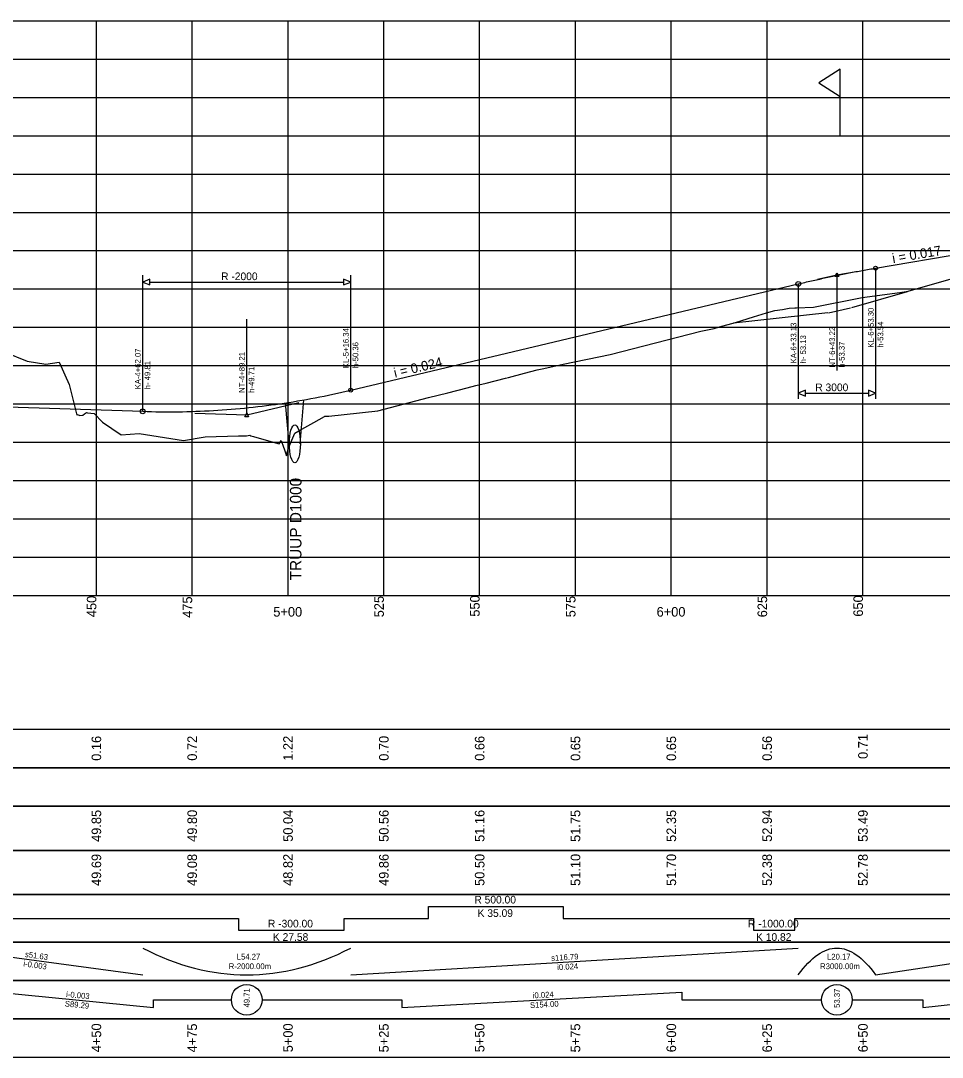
# Model space of a CAD drawing. Extents: x 655100 to 703495, y 6445581 to 6476602.
# Drawn here: x 669739.6 to 669980, y 6465749.1 to 6466019.6 of the extents above; entities that cross this region are included whole.
import ezdxf

# ---------------------------------------------------------------- set-up
doc = ezdxf.new("R2010")
doc.units = 0
for name, color, linetype in [('1_truup proj', 7, 'Continuous'), ('54', 7, 'Continuous'), ('Level 25', 7, 'Continuous'), ('Level 6', 7, 'Continuous'), ('MAAMUDEL', 7, 'Continuous'), ('Profile', 7, 'Continuous'), ('Profile Annotation', 7, 'Continuous'), ('Prop Vertical Alignment', 7, 'Continuous'), ('Prop_Benching', 7, 'Continuous'), ('TRUUP', 7, 'Continuous')]:
    doc.layers.add(name, color=color, linetype=linetype)

msp = doc.modelspace()

# ---------------------------------------------------------------- linework, layer by layer
at = {"layer": '1_truup proj'}
msp.add_line((669950.32, 6465943.38), (669956.02, 6465944.62), dxfattribs=at)
at = {"layer": '54'}
for points in [[(669299.3, 6465824.57), (670219.3, 6465824.57), (670219.3, 6465834.57), (669299.3, 6465834.57)], [(669299.3, 6465814.57), (670219.3, 6465814.57), (670219.3, 6465824.57), (669299.3, 6465824.57)], [(669299.3, 6465803.07), (670219.3, 6465803.07), (670219.3, 6465814.57), (669299.3, 6465814.57)], [(669299.3, 6465791.57), (670219.3, 6465791.57), (670219.3, 6465803.07), (669299.3, 6465803.07)], [(669299.3, 6465779.07), (670219.3, 6465779.07), (670219.3, 6465791.57), (669299.3, 6465791.57)], [(669299.3, 6465769.07), (670219.3, 6465769.07), (670219.3, 6465779.07), (669299.3, 6465779.07)], [(669299.3, 6465759.07), (670219.3, 6465759.07), (670219.3, 6465769.07), (669299.3, 6465769.07)], [(669299.3, 6465749.07), (670219.3, 6465749.07), (670219.3, 6465759.07), (669299.3, 6465759.07)]]:
    msp.add_lwpolyline(points, close=True, dxfattribs=at)
for points in [[(669759.3, 6465834.57), (669759.3, 6465834.57)], [(669784.3, 6465834.57), (669784.3, 6465834.57)], [(669809.3, 6465834.57), (669809.3, 6465834.57)], [(669834.3, 6465834.57), (669834.3, 6465834.57)], [(669859.3, 6465834.57), (669859.3, 6465834.57)], [(669884.3, 6465834.57), (669884.3, 6465834.57)], [(669909.3, 6465834.57), (669909.3, 6465834.57)], [(669934.3, 6465834.57), (669934.3, 6465834.57)], [(669959.3, 6465834.57), (669959.3, 6465834.57)], [(669759.3, 6465824.57), (669759.3, 6465824.57)], [(669784.3, 6465824.57), (669784.3, 6465824.57)], [(669809.3, 6465824.57), (669809.3, 6465824.57)], [(669834.3, 6465824.57), (669834.3, 6465824.57)], [(669859.3, 6465824.57), (669859.3, 6465824.57)], [(669884.3, 6465824.57), (669884.3, 6465824.57)], [(669909.3, 6465824.57), (669909.3, 6465824.57)], [(669934.3, 6465824.57), (669934.3, 6465824.57)], [(669959.3, 6465824.57), (669959.3, 6465824.57)], [(669759.3, 6465814.57), (669759.3, 6465814.57)], [(669784.3, 6465814.57), (669784.3, 6465814.57)], [(669809.3, 6465814.57), (669809.3, 6465814.57)], [(669834.3, 6465814.57), (669834.3, 6465814.57)], [(669859.3, 6465814.57), (669859.3, 6465814.57)], [(669884.3, 6465814.57), (669884.3, 6465814.57)], [(669909.3, 6465814.57), (669909.3, 6465814.57)], [(669934.3, 6465814.57), (669934.3, 6465814.57)], [(669959.3, 6465814.57), (669959.3, 6465814.57)], [(669759.3, 6465803.07), (669759.3, 6465803.07)], [(669784.3, 6465803.07), (669784.3, 6465803.07)], [(669809.3, 6465803.07), (669809.3, 6465803.07)], [(669834.3, 6465803.07), (669834.3, 6465803.07)], [(669859.3, 6465803.07), (669859.3, 6465803.07)], [(669884.3, 6465803.07), (669884.3, 6465803.07)], [(669909.3, 6465803.07), (669909.3, 6465803.07)], [(669934.3, 6465803.07), (669934.3, 6465803.07)], [(669959.3, 6465803.07), (669959.3, 6465803.07)], [(669796.34, 6465791.57), (669796.34, 6465791.57)], [(669823.91, 6465791.57), (669823.91, 6465791.57)], [(669845.97, 6465791.57), (669845.97, 6465791.57)], [(669881.07, 6465791.57), (669881.07, 6465791.57)], [(669930.74, 6465791.57), (669930.74, 6465791.57)], [(669941.56, 6465791.57), (669941.56, 6465791.57)], [(669771.38, 6465779.07), (669771.38, 6465779.07)], [(669825.65, 6465779.07), (669825.65, 6465779.07)], [(669942.44, 6465779.07), (669942.44, 6465779.07)], [(669962.61, 6465779.07), (669962.61, 6465779.07)], [(669771.38, 6465769.07), (669771.38, 6465769.07)], [(669825.65, 6465769.07), (669825.65, 6465769.07)], [(669942.44, 6465769.07), (669942.44, 6465769.07)], [(669962.61, 6465769.07), (669962.61, 6465769.07)], [(669759.3, 6465759.07), (669759.3, 6465759.07)], [(669784.3, 6465759.07), (669784.3, 6465759.07)], [(669809.3, 6465759.07), (669809.3, 6465759.07)], [(669834.3, 6465759.07), (669834.3, 6465759.07)], [(669859.3, 6465759.07), (669859.3, 6465759.07)], [(669884.3, 6465759.07), (669884.3, 6465759.07)], [(669909.3, 6465759.07), (669909.3, 6465759.07)], [(669934.3, 6465759.07), (669934.3, 6465759.07)], [(669959.3, 6465759.07), (669959.3, 6465759.07)]]:
    msp.add_lwpolyline(points, dxfattribs=at)
at = {"layer": 'Level 25'}
msp.add_lwpolyline([(669953.33, 6465989.57), (669953.33, 6466006.92), (669947.83, 6466003.39), (669953.34, 6465999.84)], dxfattribs=at)
at = {"layer": 'Level 6'}
msp.add_lwpolyline([(669735.24, 6465933.15), (669741.27, 6465930.69), (669746.12, 6465929.95), (669749.62, 6465930.47), (669752.22, 6465924.63), (669754.24, 6465916.66), (669754.4, 6465916.8), (669755, 6465916.57), (669755.77, 6465916.61), (669756.2, 6465916.99), (669756.75, 6465917.32), (669757.02, 6465917.23), (669758.72, 6465917.05), (669758.73, 6465917.05), (669760.91, 6465914.85), (669765.78, 6465911.54), (669770.47, 6465911.88), (669782.03, 6465910.02), (669787.71, 6465911.02), (669796.34, 6465911.22), (669798.46, 6465911.27), (669799.36, 6465911.39), (669799.58, 6465911.25), (669800.28, 6465911.06), (669804.22, 6465909.94), (669807, 6465909.15), (669807.54, 6465910.01), (669808.16, 6465908.29), (669808.33, 6465907.82), (669808.89, 6465906.03), (669809.35, 6465907.88), (669811.08, 6465911.93), (669812.1, 6465912.51), (669816.04, 6465914.74), (669818.84, 6465916.32), (669818.89, 6465916.35), (669819.01, 6465916.36), (669819.76, 6465916.4), (669819.98, 6465916.42), (669823.91, 6465916.83), (669832.71, 6465917.76), (669845.97, 6465921.21), (669850.99, 6465922.51), (669856, 6465923.78), (669858.33, 6465924.36), (669861.01, 6465925.03), (669866.03, 6465926.27), (669866.79, 6465926.45), (669871.04, 6465927.59), (669874.3, 6465928.44), (669876.05, 6465928.83), (669881.07, 6465929.91), (669893.38, 6465932.51), (669917.04, 6465938.55), (669920.51, 6465939.29), (669921.87, 6465939.71), (669926.03, 6465940.85), (669930.74, 6465942.31), (669934.14, 6465943.37), (669936.27, 6465943.94), (669938.33, 6465944.25), (669940.04, 6465944.58), (669941.56, 6465944.63), (669941.96, 6465944.64), (669946.4, 6465944.84), (669959.13, 6465947.34), (669968.96, 6465948.68), (669971.13, 6465949.01), (669979.86, 6465951.5), (669993.44, 6465955.39)], dxfattribs=at)
at = {"layer": 'MAAMUDEL'}
for p, q in [((669956.43, 6465944.71), (669970.96, 6465948.95)), ((669950.16, 6465943.31), (669925.49, 6465940.63))]:
    msp.add_line(p, q, dxfattribs=at)
at = {"layer": 'Profile'}
for p, q in [((669309.3, 6466019.57), (670209.3, 6466019.57)), ((669309.3, 6466019.57), (670209.3, 6466019.57)), ((669759.3, 6465869.57), (669759.3, 6466019.57)), ((669784.3, 6465869.57), (669784.3, 6466019.57)), ((669809.3, 6465869.57), (669809.3, 6466019.57)), ((669834.3, 6465869.57), (669834.3, 6466019.57)), ((669859.3, 6465869.57), (669859.3, 6466019.57)), ((669884.3, 6465869.57), (669884.3, 6466019.57)), ((669909.3, 6465869.57), (669909.3, 6466019.57)), ((669934.3, 6465869.57), (669934.3, 6466019.57)), ((669959.3, 6465869.57), (669959.3, 6466019.57)), ((669309.3, 6466009.57), (670209.3, 6466009.57)), ((669309.3, 6465999.57), (670209.3, 6465999.57)), ((669309.3, 6465989.57), (670209.3, 6465989.57)), ((669309.3, 6465979.57), (670209.3, 6465979.57)), ((669309.3, 6465969.57), (670209.3, 6465969.57)), ((669309.3, 6465959.57), (670209.3, 6465959.57)), ((669309.3, 6465949.57), (670209.3, 6465949.57)), ((669309.3, 6465939.57), (670209.3, 6465939.57)), ((669309.3, 6465929.57), (670209.3, 6465929.57)), ((669309.3, 6465919.57), (670209.3, 6465919.57)), ((669309.3, 6465909.57), (670209.3, 6465909.57)), ((669309.3, 6465899.57), (670209.3, 6465899.57)), ((669309.3, 6465889.57), (670209.3, 6465889.57)), ((669309.3, 6465879.57), (670209.3, 6465879.57)), ((669309.3, 6465869.57), (670209.3, 6465869.57))]:
    msp.add_line(p, q, dxfattribs=at)
at = {"layer": 'Profile Annotation'}
for points in [[(669648.62, 6465785.32), (669796.34, 6465785.32), (669796.34, 6465782.2), (669823.91, 6465782.2), (669823.91, 6465785.32), (669845.97, 6465785.32), (669845.97, 6465788.45), (669881.07, 6465788.45), (669881.07, 6465785.32), (669930.74, 6465785.32), (669930.74, 6465782.2), (669941.56, 6465782.2), (669941.56, 6465785.32), (669993.44, 6465785.32), (669993.44, 6465782.2), (670015.52, 6465782.2), (670015.52, 6465785.32), (670050.86, 6465785.32), (670050.86, 6465782.2), (670195.72, 6465782.2), (670195.72, 6465785.32), (670204.27, 6465785.32)], [(669719.74, 6465777.57), (669771.38, 6465770.57)], [(669771.38, 6465777.57), (669773.07, 6465776.73), (669774.77, 6465775.93), (669776.46, 6465775.19), (669778.16, 6465774.51), (669779.86, 6465773.88), (669781.55, 6465773.31), (669783.25, 6465772.79), (669784.94, 6465772.32), (669786.64, 6465771.91), (669788.34, 6465771.56), (669790.03, 6465771.26), (669791.73, 6465771.01), (669793.42, 6465770.82), (669795.12, 6465770.68), (669796.82, 6465770.6), (669800.21, 6465770.6), (669801.9, 6465770.68), (669803.6, 6465770.82), (669805.3, 6465771.01), (669806.99, 6465771.26), (669808.69, 6465771.56), (669810.39, 6465771.91), (669812.08, 6465772.32), (669813.78, 6465772.79), (669815.47, 6465773.31), (669817.17, 6465773.88), (669818.87, 6465774.51), (669820.56, 6465775.19), (669822.26, 6465775.93), (669823.95, 6465776.73), (669825.65, 6465777.57)], [(669825.65, 6465770.57), (669942.44, 6465777.57)], [(669942.44, 6465770.57), (669943.07, 6465771.42), (669943.7, 6465772.21), (669944.33, 6465772.95), (669944.96, 6465773.64), (669945.59, 6465774.26), (669946.22, 6465774.84), (669946.85, 6465775.36), (669947.48, 6465775.82), (669948.11, 6465776.23), (669948.74, 6465776.59), (669949.37, 6465776.89), (669950, 6465777.14), (669950.63, 6465777.33), (669951.26, 6465777.46), (669951.89, 6465777.55), (669953.15, 6465777.55), (669953.78, 6465777.46), (669954.41, 6465777.33), (669955.04, 6465777.14), (669955.67, 6465776.89), (669956.3, 6465776.59), (669956.93, 6465776.23), (669957.57, 6465775.82), (669958.2, 6465775.36), (669958.83, 6465774.84), (669959.46, 6465774.26), (669960.09, 6465773.64), (669960.72, 6465772.95), (669961.35, 6465772.21), (669961.98, 6465771.42), (669962.61, 6465770.57)], [(669962.61, 6465770.57), (670008.95, 6465777.57)], [(669713.23, 6465764.07), (669733.55, 6465764.07), (669733.55, 6465766.07), (669774.19, 6465762.07), (669774.19, 6465764.07), (669794.52, 6465764.07)], [(669802.52, 6465764.07), (669839.02, 6465764.07), (669839.02, 6465762.07), (669912.02, 6465766.07), (669912.02, 6465764.07), (669948.52, 6465764.07)], [(669956.52, 6465764.07), (669974.9, 6465764.07), (669974.9, 6465762.07), (670011.65, 6465766.07), (670011.65, 6465764.07), (670030.02, 6465764.07)]]:
    msp.add_lwpolyline(points, dxfattribs=at)
for centre in [(669798.52, 6465764.07), (669952.52, 6465764.07)]:
    msp.add_circle(centre, 4, dxfattribs=at)
at = {"layer": 'Prop Vertical Alignment'}
for p, q in [((669962.61, 6465955.01), (670008.95, 6465962.9)), ((669952.52, 6465953.29), (669957.56, 6465954.15)), ((669962.61, 6465955.01), (669962.61, 6465950.01)), ((669962.61, 6465955.01), (669962.61, 6465920.9)), ((669771.38, 6465917.64), (669771.38, 6465953.16)), ((669825.65, 6465923.16), (669825.65, 6465953.16)), ((669825.65, 6465923.16), (669942.44, 6465950.9)), ((669942.44, 6465950.9), (669942.44, 6465945.9)), ((669942.44, 6465950.9), (669942.44, 6465920.9)), ((669947.48, 6465952.1), (669952.52, 6465953.29)), ((669952.52, 6465952.61), (669952.52, 6465928.29)), ((669962.61, 6465950.01), (669962.61, 6465933.51)), ((669942.44, 6465945.9), (669942.44, 6465929.4)), ((669825.65, 6465928.16), (669825.65, 6465944.66)), ((669798.52, 6465921.72), (669798.52, 6465941.72)), ((669771.38, 6465922.64), (669771.38, 6465939.14)), ((669825.65, 6465923.16), (669825.65, 6465928.16)), ((669771.38, 6465917.64), (669771.38, 6465922.64)), ((669798.52, 6465916.72), (669798.52, 6465921.72)), ((669719.74, 6465919.39), (669771.38, 6465917.64)), ((669798.52, 6465916.72), (669812.08, 6465919.94)), ((669784.95, 6465917.18), (669798.52, 6465916.72))]:
    msp.add_line(p, q, dxfattribs=at)
for points in [[(669942.44, 6465950.9), (669942.86, 6465951), (669943.29, 6465951.1), (669943.72, 6465951.2), (669944.15, 6465951.3), (669944.58, 6465951.4), (669945.01, 6465951.5), (669945.44, 6465951.6), (669945.87, 6465951.69), (669946.3, 6465951.79), (669946.73, 6465951.89), (669947.16, 6465951.98), (669947.59, 6465952.08), (669948.01, 6465952.17), (669948.44, 6465952.26), (669948.87, 6465952.36), (669949.3, 6465952.45), (669949.73, 6465952.54), (669950.16, 6465952.63), (669950.59, 6465952.72), (669951.02, 6465952.81), (669951.45, 6465952.9), (669951.88, 6465952.99), (669952.31, 6465953.08), (669952.74, 6465953.17), (669953.17, 6465953.25), (669953.59, 6465953.34), (669954.02, 6465953.43), (669954.45, 6465953.51), (669954.88, 6465953.6), (669955.31, 6465953.68), (669955.74, 6465953.76), (669956.17, 6465953.85), (669956.6, 6465953.93), (669957.03, 6465954.01), (669957.46, 6465954.09), (669957.89, 6465954.17), (669958.32, 6465954.25), (669958.75, 6465954.33), (669959.17, 6465954.41), (669959.6, 6465954.48), (669960.03, 6465954.56), (669960.46, 6465954.64), (669960.89, 6465954.71), (669961.32, 6465954.79), (669961.75, 6465954.86), (669962.18, 6465954.94), (669962.61, 6465955.01)], [(669773.22, 6465951.38), (669823.8, 6465951.38)], [(669771.38, 6465917.64), (669772.53, 6465917.6), (669773.69, 6465917.57), (669774.84, 6465917.55), (669776, 6465917.53), (669777.15, 6465917.52), (669778.3, 6465917.52), (669779.46, 6465917.53), (669780.61, 6465917.54), (669781.77, 6465917.55), (669782.92, 6465917.58), (669784.08, 6465917.61), (669785.23, 6465917.65), (669786.39, 6465917.69), (669787.54, 6465917.74), (669788.7, 6465917.8), (669789.85, 6465917.86), (669791.01, 6465917.93), (669792.16, 6465918.01), (669793.32, 6465918.1), (669794.47, 6465918.19), (669795.63, 6465918.28), (669796.78, 6465918.39), (669797.94, 6465918.5), (669799.09, 6465918.62), (669800.25, 6465918.74), (669801.4, 6465918.87), (669802.56, 6465919.01), (669803.71, 6465919.15), (669804.87, 6465919.31), (669806.02, 6465919.46), (669807.18, 6465919.63), (669808.33, 6465919.8), (669809.48, 6465919.98), (669810.64, 6465920.16), (669811.79, 6465920.35), (669812.95, 6465920.55), (669814.1, 6465920.75), (669815.26, 6465920.96), (669816.41, 6465921.18), (669817.57, 6465921.4), (669818.72, 6465921.64), (669819.88, 6465921.87), (669821.03, 6465922.12), (669822.19, 6465922.37), (669823.34, 6465922.63), (669824.5, 6465922.89), (669825.65, 6465923.16)], [(669944.28, 6465922.4), (669960.76, 6465922.4)]]:
    msp.add_lwpolyline(points, dxfattribs=at)
for points in [[(669952.52, 6465953.79), (669953.02, 6465952.79), (669952.02, 6465952.79)], [(669771.38, 6465951.38), (669773.22, 6465950.62), (669773.22, 6465952.15)], [(669825.65, 6465951.38), (669823.8, 6465952.15), (669823.8, 6465950.62)], [(669942.44, 6465922.4), (669944.28, 6465921.63), (669944.28, 6465923.16)], [(669962.61, 6465922.4), (669960.76, 6465923.16), (669960.76, 6465921.63)], [(669798.52, 6465917.22), (669799.02, 6465916.22), (669798.02, 6465916.22)]]:
    msp.add_lwpolyline(points, close=True, dxfattribs=at)
for centre, radius in [((669962.61, 6465955.01), 0.5), ((669942.44, 6465950.9), 0.625), ((669825.65, 6465923.16), 0.5), ((669771.38, 6465917.64), 0.625)]:
    msp.add_circle(centre, radius, dxfattribs=at)
at = {"layer": 'TRUUP'}
for p, q in [((669809.64, 6465909.17), (669808.67, 6465919.82)), ((669812.51, 6465909.17), (669813.41, 6465920.63))]:
    msp.add_line(p, q, dxfattribs=at)
msp.add_ellipse((669811.08, 6465909.17), major_axis=(0, 4.98), ratio=0.287799, dxfattribs=at)

# ---------------------------------------------------------------- texts
at = {"layer": 'Profile'}
for s, p in [('450', (669759.3, 6465863.93)), ('475', (669784.3, 6465863.76)), ('525', (669834.3, 6465863.89)), ('550', (669859.3, 6465864.05)), ('575', (669884.3, 6465863.89)), ('625', (669934.3, 6465863.89)), ('650', (669959.3, 6465864.05))]:
    msp.add_text(s, height=2.5, rotation=90, dxfattribs=at).set_placement(p)
for s, p in [('5+00', (669805.46, 6465864.07)), ('6+00', (669905.46, 6465864.07))]:
    msp.add_text(s, height=2.5, dxfattribs=at).set_placement(p)
at = {"layer": 'Profile Annotation'}
for s, height, rotation, p in [('0.16', 2.5, 90, (669760.55, 6465826.44)), ('0.72', 2.5, 90, (669785.55, 6465826.46)), ('1.22', 2.5, 90, (669810.55, 6465826.46)), ('0.70', 2.5, 90, (669835.55, 6465826.45)), ('0.66', 2.5, 90, (669860.55, 6465826.44)), ('0.65', 2.5, 90, (669885.55, 6465826.42)), ('0.65', 2.5, 90, (669910.55, 6465826.42)), ('0.56', 2.5, 90, (669935.55, 6465826.44)), ('0.71', 2.5, 90, (669960.55, 6465826.92)), ('49.85', 2.5, 90, (669760.55, 6465805.27)), ('49.80', 2.5, 90, (669785.55, 6465805.29)), ('50.04', 2.5, 90, (669810.55, 6465805.29)), ('50.56', 2.5, 90, (669835.55, 6465805.28)), ('51.16', 2.5, 90, (669860.55, 6465805.28)), ('51.75', 2.5, 90, (669885.55, 6465805.27)), ('52.35', 2.5, 90, (669910.55, 6465805.27)), ('52.94', 2.5, 90, (669935.55, 6465805.29)), ('53.49', 2.5, 90, (669960.55, 6465805.28)), ('49.69', 2.5, 90, (669760.55, 6465793.78)), ('49.08', 2.5, 90, (669785.55, 6465793.78)), ('48.82', 2.5, 90, (669810.55, 6465793.8)), ('49.86', 2.5, 90, (669835.55, 6465793.78)), ('50.50', 2.5, 90, (669860.55, 6465793.79)), ('51.10', 2.5, 90, (669885.55, 6465793.79)), ('51.70', 2.5, 90, (669910.55, 6465793.79)), ('52.38', 2.5, 90, (669935.55, 6465793.78)), ('52.78', 2.5, 90, (669960.55, 6465793.78)), ('s51.63', 1.5, 352.2791, (669740.6, 6465775.25)), ('s116.79', 1.5, 3.4302, (669877.99, 6465774.21)), ('i-0.003', 1.5, 352.2791, (669740.17, 6465772.79)), ('i0.024', 1.5, 3.4302, (669879.57, 6465771.8)), ('49.71', 1.5, 90, (669799.27, 6465762.08)), ('i-0.003', 1.5, 354.3793, (669751.35, 6465764.82)), ('i0.024', 1.5, 3.1363, (669873.2, 6465764.45)), ('53.37', 1.5, 90, (669953.27, 6465761.96)), ('S89.29', 1.5, 354.3793, (669751.01, 6465762.35)), ('S154.00', 1.5, 3.1363, (669872.47, 6465761.9)), ('4+50', 2.5, 90, (669760.55, 6465750.38)), ('4+75', 2.5, 90, (669785.55, 6465750.35)), ('5+00', 2.5, 90, (669810.55, 6465750.38)), ('5+25', 2.5, 90, (669835.55, 6465750.35)), ('5+50', 2.5, 90, (669860.55, 6465750.38)), ('5+75', 2.5, 90, (669885.55, 6465750.35)), ('6+00', 2.5, 90, (669910.55, 6465750.38)), ('6+25', 2.5, 90, (669935.55, 6465750.35)), ('6+50', 2.5, 90, (669960.55, 6465750.38))]:
    msp.add_text(s, height=height, rotation=rotation, dxfattribs=at).set_placement(p)
for s, p in [('L54.27', (669795.93, 6465774.57)), ('L20.17', (669949.93, 6465774.57)), ('R-2000.00m', (669793.84, 6465772.07)), ('R3000.00m', (669948.13, 6465772.07))]:
    msp.add_text(s, height=1.5, dxfattribs=at).set_placement(p)
at = {"layer": 'Prop Vertical Alignment'}
for s, height, rotation, p in [('i = 0.017', 2.5, 9.6601, (669967.16, 6465956.29)), ('KL-6+53.30', 1.5, 90, (669962.11, 6465934.26)), ('KA-6+33.13', 1.5, 90, (669941.94, 6465930.15)), ('h-53.54', 1.5, 90, (669964.61, 6465934.26)), ('KL-5+16.34', 1.5, 90, (669825.15, 6465928.91)), ('h- 53.13', 1.5, 90, (669944.44, 6465930.15)), ('NT-6+43.22', 1.5, 90, (669952.02, 6465929.04)), ('h-50.36', 1.5, 90, (669827.65, 6465928.91)), ('h-53.37', 1.5, 90, (669954.52, 6465929.04)), ('KA-4+62.07', 1.5, 90, (669770.88, 6465923.39)), ('NT-4+89.21', 1.5, 90, (669798.02, 6465922.47)), ('h- 49.81', 1.5, 90, (669773.38, 6465923.39)), ('i = 0.024', 2.5, 13.3604, (669837.21, 6465926.42)), ('h-49.71', 1.5, 90, (669800.52, 6465922.47))]:
    msp.add_text(s, height=height, rotation=rotation, dxfattribs=at).set_placement(p)
for s, p in [('R -2000', (669791.85, 6465951.88)), ('R 3000', (669946.86, 6465922.9))]:
    msp.add_text(s, height=2, dxfattribs=at).set_placement(p)
at = {"layer": 'Prop_Benching'}
for s, p in [('R 500.00', (669857.92, 6465789.2)), ('K 35.09', (669858.77, 6465785.7)), ('R -300.00', (669804.06, 6465782.95)), ('R -1000.00', (669929.3, 6465782.95)), ('K 27.58', (669805.37, 6465779.45)), ('K 10.82', (669931.41, 6465779.45))]:
    msp.add_text(s, height=2, dxfattribs=at).set_placement(p)
at = {"layer": 'TRUUP'}
msp.add_text('TRUUP D1000', height=3, rotation=90, dxfattribs=at).set_placement((669812.8, 6465873.52))

doc.saveas('drawing.dxf')
